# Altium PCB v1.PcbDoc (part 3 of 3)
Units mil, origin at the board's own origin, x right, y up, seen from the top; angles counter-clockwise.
Board outline 2610 x 5109 mil, 2 copper layers (Top Layer, Bottom Layer), stack 62 mil thick; 307 components, 181 nets, 763 pads, 1057 vias.
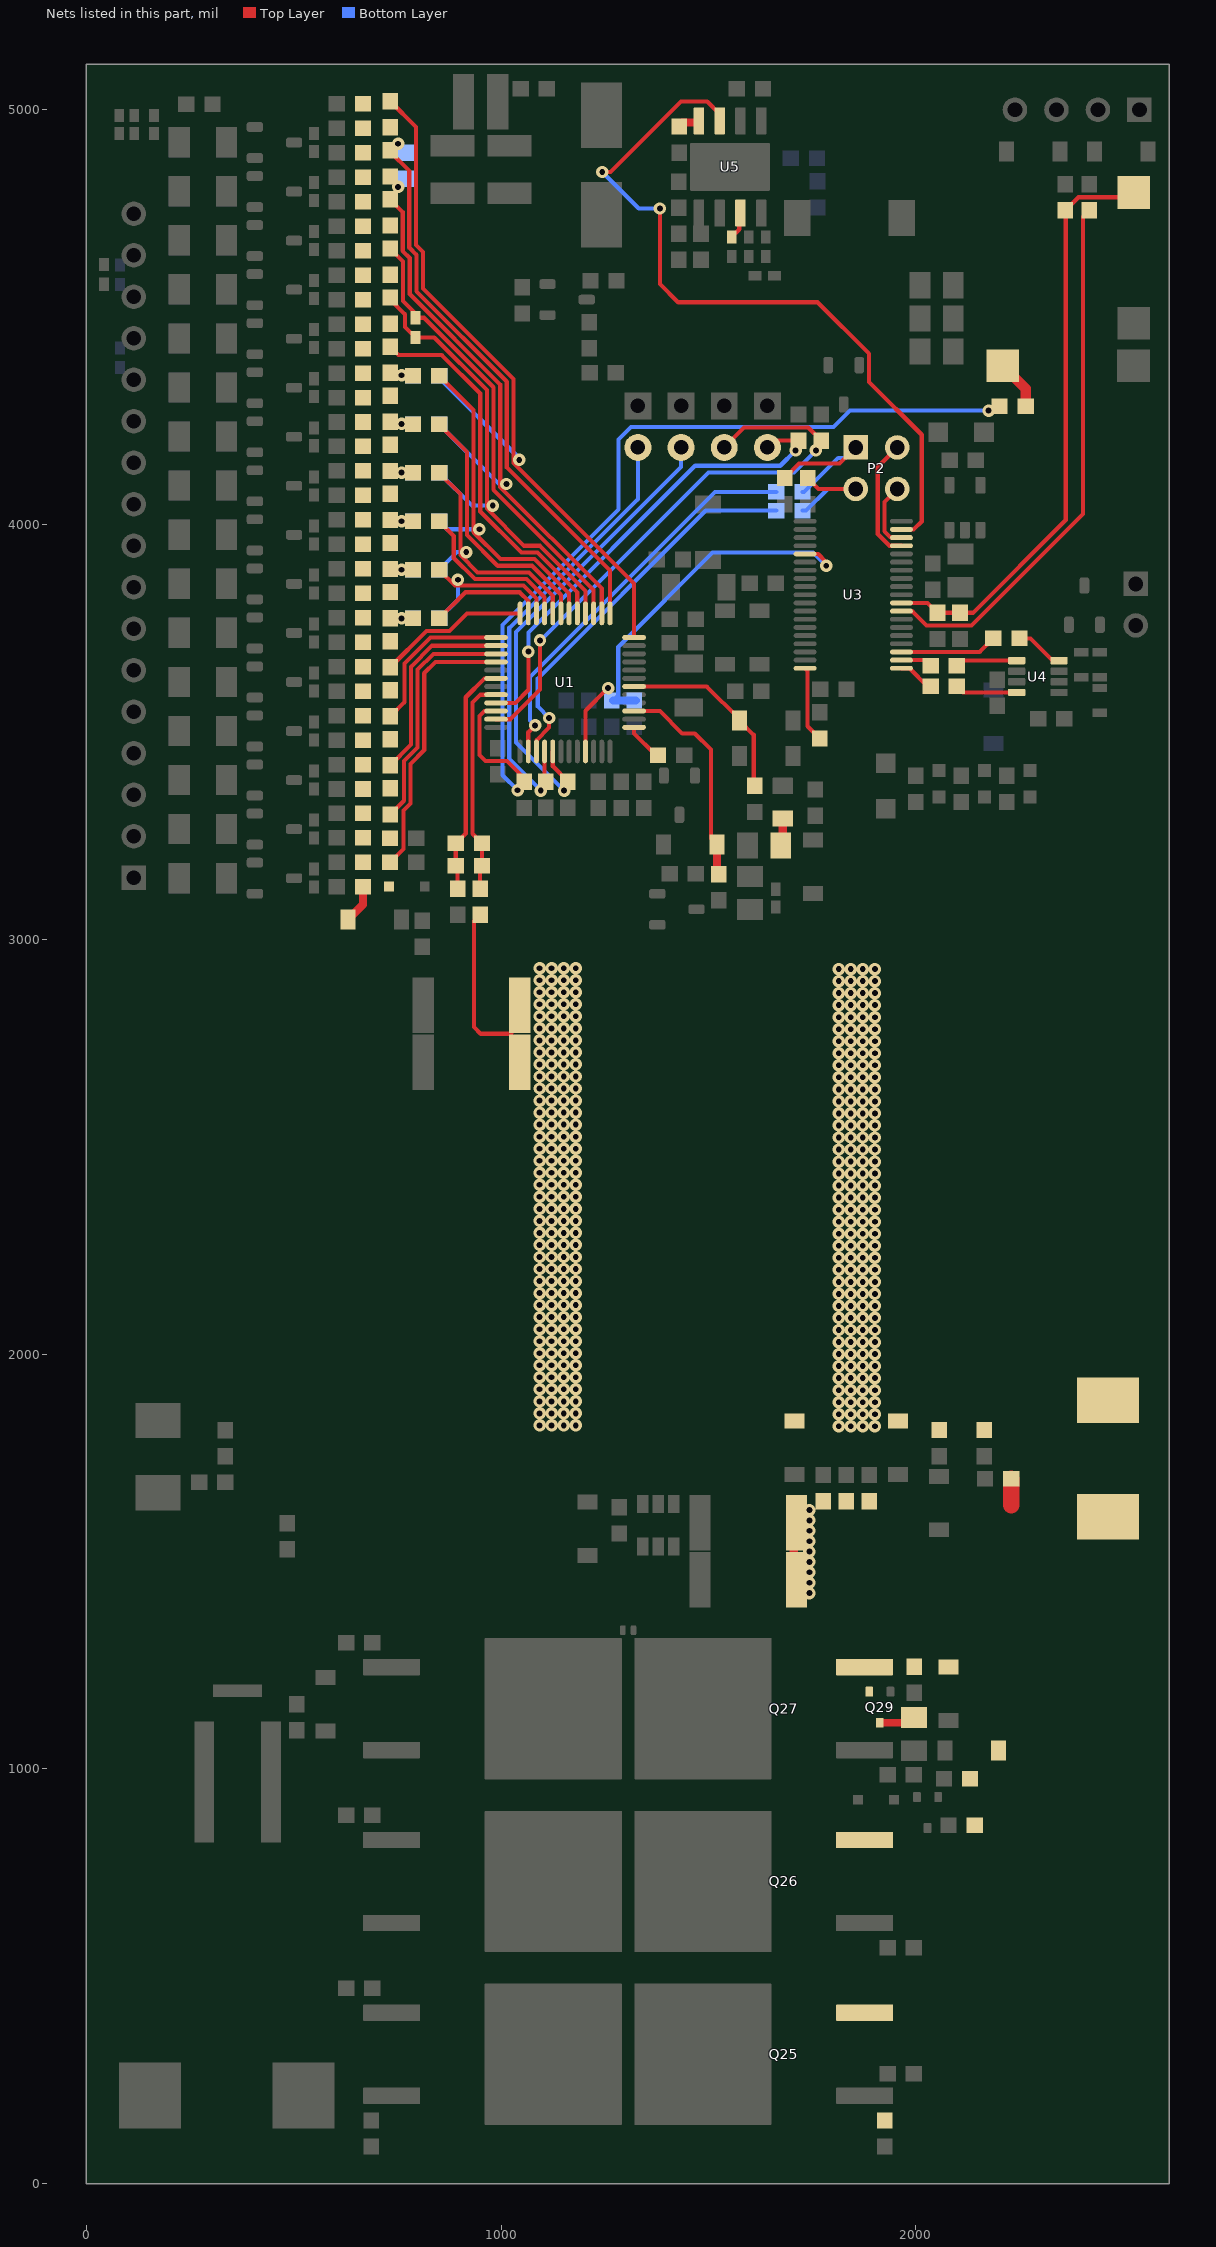
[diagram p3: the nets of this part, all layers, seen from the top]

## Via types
v1: diameter 30, hole 14, Top Layer to Bottom Layer, 1049 vias
v2: diameter 19.68, hole 7.87, Top Layer to Bottom Layer, tented both sides, 4 vias
v3: diameter 19.68, hole 7.87, Top Layer to Bottom Layer, 4 vias

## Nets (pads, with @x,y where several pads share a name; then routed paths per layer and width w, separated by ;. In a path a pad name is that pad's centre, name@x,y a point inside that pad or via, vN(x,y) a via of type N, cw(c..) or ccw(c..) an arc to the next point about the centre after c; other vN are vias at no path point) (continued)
NetQ29_3: Q29.3 R134.2 | length 69.6
  Top Layer w18: Q29.3@1913,1111.6 R134.2@1982.6,1111.6
NetR62_2: R62.2 R64.2 U1.8 | length 607.9
  Top Layer w10: R62.2@850.99,4123.97 902,4072.97 902,3925.63 943.63,3884 1067.86,3884 1124.81,3827.05 U1.8@1124.81,3785.07
  Bottom Layer w10: R64.2@850.99,3890 893.99,3933 v1(916,3933)
NetR63_2: R63.2 R66.2 U1.6 | length 855.9
  Top Layer w10: R63.2@850.99,4358 934,4274.99 934,3980.63 998.63,3916 1081.12,3916 1164.18,3832.94 U1.6@1164.18,3785.07
  Bottom Layer w10: R66.2@850.99,4007 869.99,3988 v1(948,3988)
NetR65_1: R65.1 R67.2 U1.10 | length 410.7
  Top Layer w10: R65.1@850.99,3890.01 889.01,3852 1054.61,3852 1085.44,3821.17 U1.10@1085.44,3785.07
  Bottom Layer w10: R67.2@850.99,3773 896,3818.01 v1(896,3866)
NetR68_1: R68.1 U1.7 | length 625.9
  Top Layer w10: R68.1@850.99,4241.05 918,4174.05 918,3974 992,3900 1074.49,3900 1144.5,3829.99 U1.7@1144.5,3785.07
NetR69_1: R69.1 U1.11 | length 279.6
  Top Layer w10: R69.1@850.99,3773 913.99,3836 1045,3836 1065.76,3815.24 U1.11@1065.76,3785.07
NetR70_1: R70.1 U1.9 | length 400
  Top Layer w10: R70.1@850.99,4007.03 886,3972.02 886,3919 937,3868 1061.24,3868 1105.13,3824.11 U1.9@1105.13,3785.07
NetR84_1: R84.1 S1.1 | length 120.8
  Top Layer w25: S1.1@2209.52,4382 2264.5,4327.02 R84.1@2264.5,4284
NetR87_2: R87.2 U1.26 | length 969.7
  Top Layer w10: U1.26@1065.76,3452.39 1065.76,3498.76 v1(1082,3515)
  Bottom Layer w10: v1(1082,3515) 1070,3527 1070,3632.25 1515.75,4078 R87.2@1663.5,4078
NetR88_2: R88.2 U1.27 | length 942.3
  Top Layer w10: U1.27@1085.44,3452.39 1085.44,3479.25 1116,3509.81 v1(1116,3533)
  Bottom Layer w10: v1(1116,3533) 1088.69,3560.31 1088.69,3628.31 1493.37,4033 R88.2@1663.5,4033
NetR93_1: R93.1 U1.37 | length 89
  Top Layer w10: U1.37@1320.68,3510.46 1320.68,3495.93 1370.61,3446 R93.1@1374.5,3446
NetR105_1: R105.1 U4.8 | length 117.9
  Top Layer w10: R105.1@2249.5,3725 2275.82,3725 2329.43,3671.39 U4.8@2345.18,3671.39
NetR106_1: R106.1 U4.4 | length 150.3
  Top Layer w10: R106.1@2098.5,3609 2112.88,3594.61 U4.4@2242.82,3594.61
NetR107_1: R107.1 U4.1 | length 149.5
  Top Layer w10: R107.1@2098.5,3659 2110.88,3671.39 U4.1@2242.82,3671.39
NetR116_2: R116.2 U5.4 | length 41.2
  Top Layer w20: R116.2@1435.79,4968.28 U5.4@1477,4968.28
NetR117_1: R117.1 U5.7 | length 71.4
  Top Layer w10: R117.1@1556,4692.62 1574.19,4710.81 1574.19,4753.72 U5.7@1577,4753.72
NetR132_2: R132.2 R133.2 | length 60.1
  Top Layer w20: R133.2@1679,3230.5 R132.2@1679,3290.63
PACK: D43.1 R139.1 U1.42 | length 452.4
  Top Layer w10: U1.42@1320.68,3608.89 1495.74,3608.89 1574.53,3530.1 D43.1@1574.53,3527 1609,3492.53 R139.1@1609,3378.51
PACK+: C58.1 C60.1 D39.2 D40.2 D47.1 Q25.3 Q26.3 Q27.3 Q29.2 R127.1 R128.1 R131.2 R135.2 R137.1 R140.2 R141.2 R142.2 | length 201.9
  Top Layer w20: R127.1@1705.77,1582.18 1705.77,1454.7 R128.1@1713.47,1462.4
  Top Layer w40: 2229.5,1635.5 C60.1@2229.5,1699
  other v1: 1743.28,1424 1743.28,1449 1743.28,1474 1743.28,1499 1743.28,1524 1743.28,1549 1743.28,1574 1743.28,1599 1743.28,1624
PACK-: C59.2 D45.2 D46.2 D47.2 R95.1 R112.2 R113.2 R136.1 | length 373.1
  Top Layer w10: R95.1@949.5,3058.5 935,3044.01 935,2788 951,2772 1025,2772
  other v1: 1814,1826 1843,1826 1872,1826 1901,1826 1093,1828 1122,1828 1151,1828 1180,1828 1814,1855 1843,1855 1872,1855 1901,1855 1093,1857 1122,1857 1151,1857 1180,1857 1814,1884 1843,1884 1872,1884 1901,1884 1093,1886 1122,1886 1151,1886 1180,1886 1814,1913 1843,1913 1872,1913 1901,1913 1093,1915 1122,1915 1151,1915 1180,1915 1814,1942 1843,1942 1872,1942 1901,1942 1093,1944 1122,1944 1151,1944 1180,1944 1814,1971 1843,1971 1872,1971 1901,1971 1093,1973 1122,1973 1151,1973 1180,1973 1814,2000 1843,2000 1872,2000 1901,2000 1093,2002 1122,2002 1151,2002 1180,2002 1814,2029 1843,2029 1872,2029 1901,2029 1093,2031 1122,2031 1151,2031 1180,2031 1814,2058 1843,2058 1872,2058 1901,2058 1093,2060 1122,2060 1151,2060 1180,2060 1814,2087 1843,2087 1872,2087 1901,2087 1093,2089 1122,2089 1151,2089 1180,2089 1814,2116 1843,2116 1872,2116 1901,2116 1093,2118 1122,2118 1151,2118 1180,2118 1814,2145 1843,2145 1872,2145 1901,2145 1093,2147 1122,2147 1151,2147 1180,2147 1814,2174 1843,2174 1872,2174 1901,2174 1093,2176 1122,2176 1151,2176 1180,2176 1814,2203 1843,2203 1872,2203 1901,2203 1093,2205 1122,2205 1151,2205 1180,2205 1814,2232 1843,2232 1872,2232 1901,2232 1093,2234 1122,2234 1151,2234 1180,2234 1814,2261 1843,2261 1872,2261 1901,2261 1093,2263 1122,2263 1151,2263 1180,2263 1814,2290 1843,2290 1872,2290 1901,2290 1093,2292 1122,2292 1151,2292 1180,2292 1814,2319 1843,2319 1872,2319 1901,2319 1093,2321 1122,2321 1151,2321 1180,2321 1814,2348 1843,2348 1872,2348 1901,2348 1093,2350 1122,2350 1151,2350 1180,2350 1814,2377 1843,2377 1872,2377 1901,2377 1093,2379 1122,2379 1151,2379 1180,2379 1814,2406 1843,2406 1872,2406 1901,2406 1093,2408 1122,2408 1151,2408 1180,2408 1814,2435 1843,2435 1872,2435 1901,2435 1093,2437 1122,2437 1151,2437 1180,2437 1814,2464 1843,2464 1872,2464 1901,2464 1093,2466 1122,2466 1151,2466 1180,2466 1814,2493 1843,2493 1872,2493 1901,2493 1093,2495 1122,2495 1151,2495 1180,2495 1814,2522 1843,2522 1872,2522 1901,2522 1093,2524 1122,2524 1151,2524 1180,2524 1814,2551 1843,2551 1872,2551 1901,2551 1093,2553 1122,2553 1151,2553 1180,2553 1814,2580 1843,2580 1872,2580 1901,2580 1093,2582 1122,2582 1151,2582 1180,2582 1814,2609 1843,2609 1872,2609 1901,2609 1093,2611 1122,2611 1151,2611 1180,2611 1814,2638 1843,2638 1872,2638 1901,2638 1093,2640 1122,2640 1151,2640 1180,2640 1814,2667 1843,2667 1872,2667 1901,2667 1093,2669 1122,2669 1151,2669 1180,2669 1814,2696 1843,2696 1872,2696 1901,2696 1093,2698 1122,2698 1151,2698 1180,2698 1814,2725 1843,2725 1872,2725 1901,2725 1093,2727 1122,2727 1151,2727 1180,2727 1814,2754 1843,2754 1872,2754 1901,2754 1093,2756 1122,2756 1151,2756 1180,2756 1814,2783 1843,2783 1872,2783 1901,2783 1093,2785 1122,2785 1151,2785 1180,2785 1814,2812 1843,2812 1872,2812 1901,2812 1093,2814 1122,2814 1151,2814 1180,2814 1814,2841 1843,2841 1872,2841 1901,2841 1093,2843 1122,2843 1151,2843 1180,2843 1814,2870 1843,2870 1872,2870 1901,2870 1093,2872 1122,2872 1151,2872 1180,2872 1814,2899 1843,2899 1872,2899 1901,2899 1093,2901 1122,2901 1151,2901 1180,2901 1814,2928 1843,2928 1872,2928 1901,2928 1093,2930 1122,2930 1151,2930 1180,2930
PDSG: D33.1 R125.1 U1.39 | length 531.9
  Top Layer w10: U1.39@1320.68,3549.83 1382.79,3549.83 1436.63,3496 1467,3496 1506.21,3456.79 1506.21,3242.26 D33.1@1520.47,3228
  Top Layer w20: D33.1@1520.47,3228 1520.47,3161.25 R125.1@1525,3156.71
POW_EN: U3.18 U5.3 | length 1831.1
  Top Layer w10: v1(1244,4849) 1264,4849 1434,5019 1497,5019 1527,4989 U5.3@1527,4968.28 ; v1(1383,4761) 1383,4579 1427,4535 1763,4535 1887,4411 1887,4342.63 2014,4215.63 2014,4007 1994.48,3987.48 U3.18@1965.14,3987.48
  Bottom Layer w10: v1(1244,4849) 1332,4761 v1(1383,4761)
PTC_Pull: R108.2 U3.38 | length 184.3
  Top Layer w10: U3.38@1732.86,3652.83 1738.82,3646.87 1738.3,3646.35 1738.3,3513.2 R108.2@1768,3483.5
RXD: R106.2 U3.1 | length 81
  Top Layer w10: U3.1@1965.14,3652.83 1984.17,3652.83 R106.2@2028,3609
SBCLK: R97.1 U3.8 | length 1301.6
  Top Layer w10: U3.8@1965.14,3790.63 1991.02,3790.63 2025.84,3755.81 2133.81,3755.81 2403,4025 2403,4740.99 R97.1@2418.47,4756.45
SBIO: C39.1 R98.1 R104.1 S2.1 U3.9 | length 1411.3
  Top Layer w10: U3.9@1965.14,3810.31 2028.18,3810.31 C39.1@2052,3786.5 R104.1@2106.2,3786.5 2137.5,3786.5 2361,4010 R98.1@2361,4756.45 ; R98.1@2360,4756.45 2391.55,4788 S2.1@2513.52,4788
SCL: P2.1 R87.1 R103.2 | length 338.9
  Top Layer w10: R103.2@1684,4111.5 1718.5,4146 1816,4146 P2.1@1855,4185
  Bottom Layer w10: R87.1@1726.5,4078 1730.63,4078 1812.63,4160 P2.1@1830,4160
SCL_MCU: P2.2 U3.16 | length 296.9
  Top Layer w10: P2.2@1955,4185 1908,4138 1908,3976.37 1936.26,3948.11 U3.16@1965.14,3948.11
SDA: P2.3 R88.1 R102.2 | length 295.4
  Top Layer w10: R102.2@1739,4111.5 1765.5,4085 P2.3@1855,4085
  Bottom Layer w10: R88.1@1726.5,4033 1735.44,4033 1787.44,4085 P2.3@1855,4085 P2.3@1842,4072
SDA_MCU: P2.4 U3.17 | length 162.3
  Top Layer w10: P2.4@1955,4085 1924,4054 1924,3983 1939.2,3967.8 U3.17@1965.14,3967.8
SHUT: C24.1 R90.2 U1.33 U3.24 | length 1041.5
  Top Layer w10: U1.33@1203.55,3452.39 1203.55,3550.55 v1(1258,3605) ; U3.24@1732.86,3928.43 1764.57,3928.43 1783.62,3909.38 1783.62,3900.38 v1(1784,3900)
  Bottom Layer w10: C24.1@1270.38,3574.99 1282.49,3587.11 1282.49,3704.49 1510,3932 1752,3932 v1(1784,3900)
  Bottom Layer w20: C24.1@1270.38,3574.99 R90.2@1325,3574.99
SRN: C32.2 C33.2 R95.2 U1.20 | length 524.8
  Top Layer w10: R95.2@949.5,3121.5 949.5,3172.5 C32.2@953.99,3177 C33.2@953.99,3231 931,3253.99 931,3570 950.2,3589.2 U1.20@988,3589.2
SRP: C32.1 C33.1 R96.2 U1.18 | length 565.2
  Top Layer w10: R96.2@895.5,3121.5 895.5,3172.5 C32.1@891,3177 C33.1@891,3231 915,3255 915,3583 960.57,3628.57 U1.18@988,3628.57
STB: R105.2 U3.3 | length 234.9
  Top Layer w10: U3.3@1965.14,3692.2 2153.71,3692.2 R105.2@2186.5,3725
TS1: C28.1 RT1.2 U1.21 | length 1136.7
  Top Layer w10: U1.21@988,3569.52 1034.52,3569.52 1066,3601 v1(1066,3693) ; RT1.2@1642,4185 1658.52,4201.52 C28.1@1717,4201.52
  Bottom Layer w10: v1(1066,3693) 1066,3739 1468,4141 1673,4141 v1(1710,4178)
TS2: C30.1 RT2.2 U1.23 | length 1375.8
  Top Layer w10: U1.23@987.85,3530 U1.23@988,3530.15 1022.52,3530.15 1094,3601.63 v1(1094,3720) ; RT2.2@1538,4185 1586,4233 1740.52,4233 C30.1@1772,4201.52
  Bottom Layer w10: v1(1094,3720) 1095,3720 1500,4125 1706,4125 v1(1759,4178)
TS3: C31.1 RT3.2 U1.28 | length 1061
  Top Layer w10: U1.28@1105.13,3452.39 1105.13,3382.37 C31.1@1108,3379.5
  Bottom Layer w10: v1(1096,3358) 1020,3434 1020,3750.37 1330,4060.37 RT3.2@1330,4185
TS4: C34.1 RT4.2 U1.29 | length 1127.8
  Top Layer w10: U1.29@1124.81,3452.39 1124.81,3416.63 1161,3380.44 C34.1@1161,3379.5
  Bottom Layer w10: v1(1152,3358) 1036,3474 1036,3740 1434,4138 RT4.2@1434,4185
TXD: R107.2 U3.2 | length 56.8
  Top Layer w10: U3.2@1965.14,3672.52 R107.2@2021.98,3672.52
VC0: C1.1 D9.1 D10.1 R17.2 R18.2 U1.16 | length 768.2
  Top Layer w10: C1.1@732.5,3185 764.81,3217.31 764.81,3309.69 782,3326.88 782,3422.53 815,3455.53 815,3641 841.94,3667.94 U1.16@988,3667.94
  Top Layer w20: D10.1@631.53,3047 667.5,3082.96 R17.2@667.5,3126
VC1: C2.2 C9.1 R19.2 R20.2 U1.15 | length 581.3
  Top Layer w10: C2.2@733,3300.5 766,3333.5 766,3429.16 799,3462.16 799,3649.75 836.88,3687.63 U1.15@988,3687.63
VC2: C2.1 C3.2 R21.2 R22.2 U1.14 | length 484.4
  Top Layer w10: C3.2@733,3418.79 783,3468.79 783,3656.37 833.94,3707.31 U1.14@988,3707.31
VC3: C3.1 C4.2 R23.2 R24.2 U1.13 | length 388.1
  Top Layer w10: C4.2@733,3537.08 767,3571.08 767,3664 830,3727 U1.13@988,3727
VC4: C4.1 C5.2 R25.2 R26.2 U1.12 | length 366.8
  Top Layer w10: C5.2@733,3655.36 820.64,3743 876,3743 918.07,3785.07 U1.12@1046.07,3785.07
VC5: C5.1 C6.2 R27.2 R28.2 R67.1 R69.2 | length 54.4
  Top Layer w20: C6.2@733.65,3773 R69.2@788,3773
  other v1: 760.27,3773
VC6: C6.1 C7.2 R29.2 R30.2 R64.1 R65.2 | length 53.1
  Top Layer w20: C7.2@734.92,3890.01 R65.2@788,3890.01
  other v1: 760.27,3890.2
VC7: C7.1 C8.2 R31.2 R32.2 R66.1 R70.2 | length 51.8
  Top Layer w20: C8.2@736.19,4007.03 R70.2@788,4007.03
  other v1: 760.27,4007.4
VC8: C8.1 C10.2 R33.2 R50.1 R51.2 R62.1 | length 50.5
  Top Layer w20: C10.2@737.53,4123.97 R62.1@788,4123.97
  other v1: 760.27,4124.6
VC9: C10.1 C11.2 R49.1 R52.2 R53.2 R68.2 | length 49.3
  Top Layer w20: C11.2@738.74,4241.05 R68.2@788,4241.05
  other v1: 760.27,4241.8
VC10: C11.1 C12.2 R48.1 R54.2 R55.2 R63.1 | length 47.9
  Top Layer w20: C12.2@740.08,4358 R63.1@788,4358
  other v1: 760.27,4359
VC11: C12.1 C13.2 R56.2 R57.2 U1.5 | length 913.3
  Top Layer w10: C12.1@733,4428.07 753.07,4408 857,4408 950,4315 950,4031 1049,3932 1087.75,3932 1183.87,3835.88 U1.5@1183.87,3785.07
VC12: C13.1 C14.2 R46.1 R50.2 R58.2 R59.2 U1.4 | length 1167
  Top Layer w10: C13.1@733,4546.35 733,4542 769,4506 769,4475.38 R46.1@794,4450.38 839.11,4450.38 966,4323.49 966,4037.63 1055.63,3948 1094.37,3948 1203.55,3838.82 U1.4@1203.55,3785.07
  Bottom Layer w10: R50.2@850.99,4124 929.99,4045 v1(980,4045)
VC13: C14.1 C20.2 R46.2 R60.2 R78.2 U1.3 | length 1094.6
  Top Layer w10: C14.1@733,4664.64 764,4633.64 764,4537.98 794,4507.98 R46.2@794,4497.62 814.5,4497.62 982,4330.12 982,4083 1223.24,3841.76 U1.3@1223.24,3785.07
VC14: C20.1 C21.2 R35.2 R49.2 R79.2 R80.2 U1.2 | length 1430.7
  Top Layer w10: C20.1@733,4782.92 763,4752.92 763,4659 780,4642 780,4554.75 998,4336.75 998,4089.63 1242.92,3844.71 U1.2@1242.92,3785.07
  Bottom Layer w10: R49.2@850.99,4241 994.99,4097 v1(1013,4097)
  other v1: 752,4813
VC15: C21.1 C22.2 R35.1 R81.2 R82.2 U1.1 | length 1331.3
  Top Layer w10: C21.1@733,4897 779,4851 779,4666.37 796,4649.37 796,4561.37 1014,4343.37 1014,4137 1262.61,3888.39 U1.1@1262.61,3785.07
  other v1: 752,4917
VC16: C22.1 R48.2 R83.2 U1.48 | length 1818.9
  Top Layer w10: C22.1@733,5019.5 795,4957.5 795,4673 812,4656 812,4568 1030,4350 1030,4148 1320.68,3857.32 U1.48@1320.68,3727
  Bottom Layer w10: R48.2@850.99,4358 850.99,4352.01 1044,4159 v1(1044,4155)
WAKE: C17.1 R84.2 U1.22 | length 2175.5
  Top Layer w10: U1.22@988,3549.83 959.83,3549.83 948,3538 948,3444 962.46,3429.54 1014.46,3429.54 1056.34,3387.66 C17.1@1056.34,3379.23
  Bottom Layer w10: v1(1040,3359) 1004,3395 1004,3757 1283,4036 1283,4204 1313,4234 1801,4234 1841,4274 v1(2175,4274)
pads on no net: RT5.1S RT5.2S U1.19 U1.40 U1.44 U3.12 U3.13 U3.14 U3.15 U3.25 U3.26 U3.27 U3.29 U3.30 U3.31 U3.32 U3.33 U3.34 U3.35 U3.37 U5.6 U5.9@1552,4861

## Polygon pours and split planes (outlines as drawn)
NetD32_1 on Top Layer "Top Layer-No Net 7" (solid, remove dead copper, pour order 28): 654,1399 654,1135 488,1135 488,1231 536,1279 536,1399
GND on Top Layer "Top Layer-No Net 18" (solid, remove dead copper, pour order 100): 2600,4525 2600,3511 2166,3511 2136,3541 2136,3729 2420,4013 2420,4525
GND on Top Layer "Top Layer-No Net 23" (solid, remove dead copper, pour order 80): 1185.73,4638 868,4638 868,4095 1185.73,4095
NetC44_1 on Top Layer "Top Layer-No Net 16" (solid, remove dead copper, pour order 76): 936,4886 936,5085 778,5085 778,5070 830,5018 830,4886
NetC45_1 on Top Layer "Top Layer-No Net 17" (solid, remove dead copper, pour order 60): 967,5085 967,4886 1075,4886 1075,5085
GND on Top Layer "Top Layer-No Net 19" (solid, remove dead copper, pour order 64): 1404,4796 1273,4665 830,4665 830,4825 1254,4825 1362.49,4933.49 1649,4935 1649,4796
PACK+ on Top Layer "Top Layer-No Net 11" (solid, remove dead copper, pour order 38): 2589,126 2589,268 2589,1665 1680,1665 1680,126
NetC57_2 on Top Layer "Top Layer-No Net 10" (solid, remove dead copper, pour order 36): 422,1119.44 861,1119.44 861,25 422,25
PACK- on Top Layer "Top Layer-No Net 9" (solid, pour order 32): 1019,3003 1019,1794 2590,1794 2590,3003
BAT+ on Top Layer "Top Layer-No Net 6" (solid, pour order 26): 29,1710 29,19 399,19 399,1025 292,1132 292,1710
GND on Top Layer "Top Layer-No Net 4" (solid, remove dead copper, pour order 10): 1795.27,3060 1795.27,3576.73 1752,3620 1752,4173 2139,4173 2139,3690 1895,3690 1895,3060
GND on Top Layer "Top Layer-No Net 2" (solid, remove dead copper, pour order 6): 1241,4553 1241,4038 1309,3970 1801,3970 1801,4553
NetD34_1 on Top Layer "Top Layer-No Net 1" (solid, pour order 2): 1356,1558 1325,1589 1182,1589 1182,1496 1356,1496
GND on Top Layer "Top Layer-No Net 13" (solid, remove dead copper, pour order 42): 776,3297 776,3792 1342,3792 1342,3437 904,3437 904,3297
GND on Top Layer "Top Layer-No Net 14" (solid, remove dead copper, pour order 44): 982.48,3023 982.48,3269 944,3269 944,3419 1410,3419 1410,3023
GND on Top Layer "Top Layer-No Net 3" (solid, remove dead copper, pour order 46): 776,3023 776,3338 904,3338 904,3255.7 865.32,3255.7 865.32,3023
NetD38_1 on Top Layer "Top Layer-No Net" (solid, remove dead copper, pour order 82): 2093.54,1072.52 2093.54,957 1963,957 1963,1072.52
NetQ24_1 on Top Layer "Top Layer-No Net 8" (solid, remove dead copper, pour order 84): 1363,1713 1363,1389 1566,1389 1566,1713
NetD34_1 on Top Layer "Top Layer-No Net 12" (solid, remove dead copper, pour order 90): 1664,57 1664,1346 1634,1376 1225,1376 1093,1508 1093,1673 1029,1737 887,1737 887,57
GND on Top Layer "Top Layer-No Net 15" (solid, pour order 92): 1449,3880 1449,3693 1650,3693 1662,3681 1662,3430 1682,3410 1722,3410 1722,3880
NetC50_2 on Top Layer "Top Layer-No Net 22" (solid, remove dead copper, pour order 94): 1410,4783 1501,4783 1501,4681 1410,4681
GND on Top Layer "Top Layer-No Net 21" (solid, remove dead copper, pour order 68): 2057,4753 2014,4796 1610,4796 1610,5079 2157,5079 2157,4384 2057,4384
GND on Bottom Layer "Bottom Layer-No Net 1" (solid, remove dead copper, pour order 102): 1719,4649 1107,4649 1107,5080 1719,5080
GND on Bottom Layer "Bottom Layer-No Net 6" (solid, remove dead copper, pour order 74): 792,5053 880,4965 880,4648 1048,4648 1048,5082 792,5082
GND on Bottom Layer "Bottom Layer-No Net" (solid, remove dead copper, pour order 98): 2187,5082 2600,5082 2600,3022 787,3022 787,4621 1812,4621 2187,4621
PACK- on Bottom Layer "Top Layer-No Net 9" (solid, pour order 34): 955,3003 955,1797 2590,1797 2590,3003
GND on Bottom Layer "Bottom Layer-No Net 3" (solid, remove dead copper, pour order 52): 859,3201 787,3201 787,3022 859,3022
NetD34_1 on Bottom Layer "Bottom Layer-No Net 2" (solid, remove dead copper, pour order 88): 771,1734 645,1608 645,25 1967,25 1967,1367 1213,1367 1196,1384 1196,1579 1041,1734

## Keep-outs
Keep-Out Layer:
  text ".Layer_Name" at 577,-858.49 h60

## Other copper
Top Layer:
  rectangle net CANL: 2493,3726 2600,3786
  rectangle net CANH: 2493,3826 2600,3886
  rectangle net BAT-: 30,1796 839,3003
  rectangle net VC0: 647.5,3104.5 751.5,3205.5
  rectangle net VC1: 648,3221.5 752,3322.5
  rectangle net VC0: 647,3107 688,3204
  rectangle net VC2: 648,3338.29 752,3439.29
  rectangle net VC3: 648,3456.57 752,3557.57
  rectangle net VC4: 648,3574.86 752,3675.86
  rectangle net VC5: 648,3693.14 752,3794.14
  rectangle net VC6: 648,3811.43 752,3912.43
  rectangle net VC7: 648,3929.71 752,4030.71
  rectangle net VC8: 648,4048 752,4149
  rectangle net VC9: 648,4166.29 752,4267.29
  rectangle net VC10: 648,4284.57 752,4385.57
  rectangle net VC11: 648,4402.86 752,4503.86
  rectangle net VC12: 648,4521.14 752,4622.14
  rectangle net VC13: 648,4639.43 752,4740.43
  rectangle net VC14: 648,4757.71 752,4858.71
  rectangle net VC15: 648,4876 752,4977
  rectangle net VC16: 648,4994 752,5039
  rectangle net NetD34_2: 1183,1610 1356,1661
  text ".Layer_Name" at 577,-858.49 h60
Bottom Layer:
  rectangle net GND: 1447,4812 1648,4911
  rectangle net NetQ24_1: 1222,1387.34 1563,1692
  rectangle net BAT-: 30,1796 890,3003
  rectangle net NetQ16_3: 280,4877 729,4976.51
  rectangle net NetQ15_3: 262,4749.26 729,4851
  rectangle net NetQ6_3: 263,3685.94 736,3794.94
  rectangle net NetQ7_3: 262,3804.2 736,3913.2
  rectangle net NetQ8_3: 262,3922.46 736,4031.46
  rectangle net NetQ9_3: 262,4040.71 736,4149.71
  rectangle net NetQ10_3: 262,4158.97 736,4267.97
  rectangle net NetQ11_3: 262,4277.23 736,4386.23
  rectangle net NetQ5_3: 263,3566.68 774,3675.68
  rectangle net NetQ4_3: 263,3448.43 774,3557.43
  rectangle net NetQ3_3: 263,3330.17 774,3439.17
  rectangle net NetQ2_3: 263,3211.91 774,3320.91
  rectangle net NetQ1_3: 263,3093.66 774,3202.66
  rectangle net NetQ13_3: 262,4512.74 775,4621.74
  rectangle net NetQ14_3: 262,4631 814,4740
  rectangle net NetQ12_3: 262,4394.49 775,4503.49
  rectangle net PACK+: 1590,1387 1967,1692
  text ".Layer_Name" at 577,-858.49 h60

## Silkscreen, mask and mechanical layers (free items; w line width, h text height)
Top Overlay:
  text "SCL" at 1871,4248 h30
  text "PACK-" at 2347,2548 h60 r270
  text "BAT-" at 275,2307 h60 r90
  text "PACK+" at 2350,819 h60 r270
  text "BAT+" at 270,500 h60 r90
  text ".Layer_Name" at 577,-858.49 h60
Bottom Overlay:
  text "CAUTION" at 557,234 h60
  text "READ USER GUIDE" at 660,170 h60
  text "BEFPRE USE" at 584,103 h60
  text ".Layer_Name" at 577,-858.49 h60
Top Paste:
  rectangle: 2493,3726 2600,3786
  rectangle: 2493,3826 2600,3886
  rectangle: 2441,2166 2582,2693
  rectangle: 37,2158 178,2685
  rectangle: 34,463 175,990
  rectangle: 2440,463 2581,990
  text ".Layer_Name" at 577,-858.49 h60
Bottom Paste:
  text ".Layer_Name" at 577,-858.49 h60
Top Solder:
  rectangle: 2493,3726 2600,3786
  rectangle: 2493,3826 2600,3886
  rectangle: 2441,2166 2582,2693
  rectangle: 37,2158 178,2685
  rectangle: 34,463 175,990
  rectangle: 2440,463 2581,990
  text ".Layer_Name" at 577,-858.49 h60
  text ".Layer_Name" at 577,-858.49 h60
Bottom Solder:
  text ".Layer_Name" at 577,-858.49 h60
Drill Guide:
  text ".Layer_Name" at 577,-858.49 h60
M1 Board Outline:
  the board outline again, w10
  text ".Layer_Name" at 577,-858.49 h60
M2 Board Dimensions:
  rectangle: 0,-275 125,-150
  rectangle: 125,-400 500,-275
  lines w7: 0,-275 1000,-275 ; 125,-400 125,-150 ; 250,-400 250,-150 ; 500,-400 500,-150 ; 750,-400 750,-150 ; 0,-400 1000,-400 1000,-150 0,-150 0,-400
  text ".Layer_Name" at 577,-858.49 h60
M3 3D STEP Top:
  text ".Layer_Name" at 577,-858.49 h60
M4 3D STEP Bottom:
  text ".Layer_Name" at 577,-858.49 h60
M5 Assembly Top:
  lines w10: -292,-930.17 6308,-930.17 ; -292,-726.83 6310,-726.83 ; -292,-523.5 -292,-1133.5 3713,-1133.5 6310,-1133.5 6310,-523.5 -291.5,-523.5 -291.5,-1133.5 1284,-1133.5 ; 2173,-1133.5 2173,-523.5 ; 3440,-726.83 3440,-523.5 ; 4280,-726.83 4280,-523.5 ; 4902,-1140 4902,-937.17
  text "COMPONENTS MARKED 'DNP' SHOULD NOT BE POPULATED." at 1153.5,-318.5 h60
  text "ASSEMBLY VARIANT:" at 1153,-434 h60
  text ".VariantName" at 2189,-434 h60
  text "PCB VIEWED FROM TOP SIDE" at -228.5,-655.67 h60
  text "BOARD #:" at 2248,-655.67 h60
  text ".PRJ_Number" at 2793.5,-655.67 h60
  text "REV:" at 3638,-655.67 h60
  text ".PCB_Rev" at 3929.5,-655.67 h60
  text "SVN REV:" at 4476,-655.67 h60
  text ".VersionControl_RevNumber" at 4982,-655.67 h60
  text "TID #:" at 2248,-859 h60
  text ".TID" at 2793.5,-859 h60
  text "PLOT NAME =" at -228.5,-1064.34 h60
  text ".plot_File_Name" at 577,-1064.34 h60
  text "GENERATED    :" at 2250,-1064.34 h60
  text ".Print_Date" at 3119.5,-1064.34 h60
  text ".Print_Time" at 3848.5,-1064.34 h60
  text "TEXAS INSTRUMENTS" at 5113,-1064.34 h60
M6 Assembly Bottom:
  lines w10: -292.5,-727.33 6309.5,-727.33 ; -290.5,-930.67 6309.5,-930.67 ; 1115.5,-1140.5 1115.5,-937.67 ; 1737.5,-727.33 1737.5,-524 ; 2577.5,-727.33 2577.5,-524 ; 3844.5,-1134 3844.5,-524 ; 4733.5,-1134 6309,-1134 6309,-524 -292.5,-524 -292.5,-1134 2304.5,-1134 6309.5,-1134 6309.5,-524
  text "COMPONENTS MARKED 'DNP' SHOULD NOT BE POPULATED." at 6102,-318 h60
  text ".VariantName" at 5058,-434 h60
  text "ASSEMBLY VARIANT:" at 6097,-434 h60
  text ".VersionControl_RevNumber" at 1035.5,-656.17 h60
  text "SVN REV:" at 1541.5,-656.17 h60
  text ".PCB_Rev" at 2088,-656.17 h60
  text "REV:" at 2379.5,-656.17 h60
  text ".PRJ_Number" at 3224,-656.17 h60
  text "BOARD #:" at 3769.5,-656.17 h60
  text "PCB VIEWED FROM BOTTOM SIDE" at 6246,-656.17 h60
  text ".TID" at 3224,-859.5 h60
  text "TID #:" at 3769.5,-859.5 h60
  text "TEXAS INSTRUMENTS" at 904.5,-1064.84 h60
  text ".Print_Time" at 2169,-1064.84 h60
  text ".Print_Date" at 2898,-1064.84 h60
  text "GENERATED    :" at 3767.5,-1064.84 h60
  text ".plot_File_Name" at 5440.5,-1064.84 h60
  text "PLOT NAME =" at 6246,-1064.84 h60
M9 Title Sheet:
  drawing of 57 lines, arcs and shapes, not listed
  text "1" at 739.84,8036.5 h70
  text "2" at 3235.5,8036.5 h70
  text "3" at 5724.84,8036.5 h70
  text "4" at 8231.51,8036.5 h70
  text "5" at 10730.5,8036.5 h70
  text "6" at 13235.5,8036.5 h70
  text "A" at -416.5,6893.5 h70
  text "A" at 14383.5,6893.5 h70
  text "B" at -416.5,4513.5 h70
  text "B" at 14383.5,4513.5 h70
  text "C" at -416.5,2138.5 h70
  text "C" at 14383.5,2138.5 h70
  text "PROJECT TITLE:" at 11343.5,277.5 h45
  text ".PRJ_Title" at 11393.5,144.17 h70
  text "DESIGNED FOR:" at 11343.5,-23.5 h45
  text ".PRJ_Customer" at 11393.5,-163.5 h70
  text "D" at -416.5,-231.5 h70
  text "D" at 14383.5,-231.5 h70
  text "FILE NAME:" at 11343.5,-323.5 h45
  text ".PCB_File_Name_No_Path" at 11393.5,-443.5 h70
  text "Texas Instruments (TI) and/or its licensors do not warrant the accuracy or completeness of this specification" at 6374,-605.34 h45
  text "ENGINEER:" at 11343.5,-613.5 h45
  text "LAYOUT BY:" at 12848.5,-613.5 h45
  text "or any information contained therein. TI and/or its licensors do not warrant that this design will meet" at 6329.01,-718 h45
  text ".PRJ_Engineer" at 11393.5,-768.49 h70
  text ".PCB_Layout" at 12899,-768.49 h70
  text "the specifications, will be suitable for your application or fit for any particular purpose, or will operate in" at 6329.01,-830.67 h45
  text ".Layer_Name" at 577,-858.49 h60
  text "ALTIUM DESIGNER VERSION:" at 12848.5,-923.5 h45
  text "an implementation. TI and/or its licensors do not warrant that the design is production worthy. You should" at 6329.01,-943.33 h45
  text "completely validate and test your design implementation to confirm the system functionality for your application." at 6374,-1056 h45
  text ".print_Scale" at 11393.5,-1056.83 h70
  text ".Application_BuildNumber" at 12899,-1056.83 h70
  text "1" at 739.84,-1263.5 h70
  text "2" at 3235.5,-1263.5 h70
  text "3" at 5724.84,-1263.5 h70
  text "4" at 8231.51,-1263.5 h70
  text "5" at 10730.5,-1263.5 h70
  text "6" at 13235.5,-1263.5 h70
M10 Fab Notes:
  drawing of 189 lines, arcs and shapes, not listed
  text "DESIGN INFORMATION" at 12382.02,6356.17 h60
  text "MIN. TRACK WIDTH:" at 11737.46,6224.05 h60
  text "8" at 12833.7,6224.05 h60
  text "MIL" at 12988.46,6224.05 h60
  text "MIN. CLEARANCE:" at 11737.46,6099.92 h60
  text "0.2" at 12773.7,6099.93 h60
  text "mm" at 12988.46,6099.92 h60
  text "MIN. VIA PAD SIZE:" at 11737.46,5975.8 h60
  text "24" at 12803.71,5975.8 h60
  text "MIL" at 12988.46,5975.8 h60
  text "0.05mm (2MIL)" at 12432.46,5845.9 h60
  text "MINIMUM ANNULAR RING" at 11408.23,5837.67 h60
  text "EXTERNAL" at 13140.46,5837.67 h60
  text "PER" at 11608.23,5727.55 h60
  text "IPC-D-275 CLASS 2 LEVEL C" at 11828.23,5727.54 h60
  text "MIL, HOLES" at 13316.46,5627.07 h60
  text "+/-" at 12924,5618.48 h60
  text "+/-" at 13778,5618.48 h60
  text "REGISTRATION TOLERANCES:" at 11408.23,5617.42 h60
  text "METAL" at 12608,5617.42 h60
  text "5" at 13184.2,5617.42 h60
  text "3" at 14017.2,5617.42 h60
  text "MIL" at 14133.46,5617.42 h60
  text "HOLE SIZE TOLERANCE (UNLESS OTHERWISE SPECIFIED):" at 11408.23,5519.1 h60
  text "+/-" at 13778,5516.23 h60
  text "3" at 14017.2,5515.17 h60
  text "MIL" at 14133.46,5515.17 h60
  text "MATERIAL:" at 11333.46,5377.52 h60
  text "FR-4 High Tg" at 12319.9,5249 h60
  text "X" at 12175.46,5241.01 h60
  text "FR-408" at 11754.46,5236.49 h60
  text "OTHER" at 13242.46,5236.49 h60
  text "62 MIL (1.6mm) +/-10%" at 12074.56,5093.46 h60
  text "X" at 11954.46,5091.01 h60
  text "THICKNESS:" at 11408.23,5085.24 h60
  text "OTHER" at 13359.46,5085.24 h60
  text "TOLERANCE:" at 11408.23,4946.92 h60
  text "X" at 12256.46,4946.92 h60
  text "ANSI IPC-6012 TYPE 3 CLASS 2" at 12434.48,4946.92 h60
  text "OTHER +/-" at 12434.46,4802.73 h60
  text "BOW & TWIST:" at 11408.23,4657.54 h60
  text "X" at 12256.46,4657.54 h60
  text "ANSI IPC-6012 TYPE 3 CLASS 2" at 12434.48,4657.54 h60
  text "OTHER +/-" at 12434.46,4510.85 h60
  text "DRILLING:" at 11333.46,4380.23 h60
  text "NC_DRILL FILES" at 13094.46,4275.04 h60
  text "REFERENCE:" at 11408.23,4271.1 h60
  text "X" at 12065.46,4271.01 h60
  text "AS SHOWN" at 12243.46,4271.1 h60
  text "X" at 12966.46,4271.1 h60
  text "OTHER" at 13392.46,4128.85 h60
  text "PTH COPPER THICKNESS:" at 11407.91,4125.32 h60
  text "X" at 12547.14,4125.32 h60
  text "20-30 um" at 12675.14,4125.32 h60
  text "BOARD FINISH:" at 11333.46,3977.73 h60
  text "SILKSCREEN:" at 11488.68,3867.6 h60
  text "X" at 12446.46,3867.6 h60
  text "TOP" at 12563.46,3867.6 h60
  text "X" at 12956.46,3867.6 h60
  text "BOTTOM" at 13074.46,3867.6 h60
  text "SILKSCREEN COLOR:" at 11488.68,3712.41 h60
  text "X" at 12445.46,3712.41 h60
  text "WHITE" at 12563.46,3712.41 h60
  text "OTHER" at 13074.46,3712.41 h60
  text "X" at 12576.46,3568.96 h60
  text "GREEN" at 12694.46,3568.96 h60
  text "OTHER" at 13312.46,3568.96 h60
  text "SOLDER RESIST COLOR:" at 11488.68,3562.1 h60
  text "X" at 12576.46,3414.71 h60
  text "MATTE" at 12694.46,3414.71 h60
  text "SEMI-GLOSS" at 13312,3414.07 h60
  text "IMMERSION GOLD (ENIG)" at 12394.46,3241.94 h60
  text "ENEPIG" at 13732,3234.72 h60
  text "SURFACE FINISH:" at 11333.46,3233.72 h60
  text "X" at 12216.46,3233.72 h60
  text "IMM. TIN/SILVER OR EQUIV" at 11663,3096.4 h60
  text "OTHER" at 13094.46,3092.47 h60
  text "ARRAY/PANEL:" at 11333.46,2937.09 h60
  text "CUT AND TRIM PER M1 BOARD OUTLINE" at 12394.46,2928.87 h60
  text "N.C. ROUTE" at 12394.46,2792.9 h60
  text "X" at 13082.46,2792.9 h60
  text "V. SCORE" at 13260.46,2792.9 h60
  text "CERTIFICATION:" at 11333.46,2663.77 h60
  text "MATERIALS AND WORKMANSHIP FOR ALL PCBS" at 12058.46,2663.77 h60
  text "TO MEET OR EXCEED THE REQUIREMENTS OF:" at 12058.46,2569.71 h60
  text "X" at 11695.97,2441.08 h60
  text "ANSI IPC-A-600F CLASS ->" at 11823.96,2441.08 h60
  text "X" at 13471.97,2441.08 h60
  text "2" at 13581.96,2441.08 h60
  text "1" at 13266.96,2439.58 h60
  text "3" at 13935.96,2439.58 h60
  text "X" at 12507.97,2293.39 h60
  text "RoHS" at 12635.96,2293.39 h60
  text "OTHER" at 13280.36,2293.39 h60
  text "PER ORDER" at 13677.42,2293.39 h60
  text "ALL BOARDS MUST MEET OR EXCEED UL94-V0 REQUIREMENTS." at 11361,2139.57 h60
  text "PCB MUST BEAR THE UL94V-0 UL REGISTERED MATERIAL ID NUMBER" at 11361,2023.5 h60
  text "ADDITIONAL REQUIREMENTS:" at 11333.46,1854.08 h60
  text "MICROSECTION:" at 11408.23,1746.95 h60
  text "YES" at 12313.96,1746.95 h60
  text "REQUIRED" at 13175.46,1602.62 h60
  text "BARE BOARD ELEC. TEST:" at 11408.23,1599.76 h60
  text "NONE" at 12713.96,1599.76 h60
  text "X" at 13057.46,1599.76 h60
  text "PER ORDER" at 13767.46,1599.76 h60
  text "XX MIL VIAS REQUIRE NON-CONDUCTIVE FILL AND PLANARIZE" at 11576.38,1394.82 h59
  text "XX MIL VIAS REQUIRE CONDUCTIVE FILL AND PLANARIZE" at 11584.38,1290.84 h60
  text "OUTER XX MIL TRACES REQUIRE 50 OHM SINGLE-ENDED IMPEDANCE" at 11583.39,1127.46 h58
  text "LAYER 2 & 3 (INNER LAYERS) XX MIL WIDE, XX MIL SPACE / TRACES REQUIRE 100 OHM DIFFERENTIAL IMPEDANCE" at 11575.39,891.74 h60
  text ".Layer_Name" at 577,-858.49 h60
M11 Gerber Information:
  lines w10: -292,-930.17 6308,-930.17 ; -292,-726.83 6310,-726.83 ; -292,-523.5 -292,-1133.5 3713,-1133.5 6310,-1133.5 6310,-523.5 -291.5,-523.5 -291.5,-1133.5 1284,-1133.5 ; 2173,-1133.5 2173,-523.5 ; 3440,-726.83 3440,-523.5 ; 4280,-726.83 4280,-523.5 ; 4902,-1140 4902,-937.17
  text "ALL ARTWORK VIEWED FROM TOP SIDE" at -228.5,-655.67 h60
  text "BOARD #:" at 2248,-655.67 h60
  text ".PRJ_Number" at 2793.5,-655.67 h60
  text "REV:" at 3638,-655.67 h60
  text ".PCB_Rev" at 3929.5,-655.67 h60
  text "SVN REV:" at 4476,-655.67 h60
  text ".VersionControl_RevNumber" at 4982,-655.67 h60
  text "LAYER NAME =" at -228.5,-858.49 h60
  text "TID #:" at 2248,-859 h60
  text ".TID" at 2793.5,-859 h60
  text "PLOT NAME =" at -228.5,-1064.34 h60
  text ".plot_File_Name" at 577,-1064.34 h60
  text "GENERATED    :" at 2250,-1064.34 h60
  text ".Print_Date" at 3119.5,-1064.34 h60
  text ".Print_Time" at 3848.5,-1064.34 h60
  text "TEXAS INSTRUMENTS" at 5113,-1064.34 h60
M12 Stackup:
  drawing of 530 lines, arcs and shapes, not listed
  text "Layer" at 9797.84,7830 h60
  text "Layer" at 9797.84,7830 h60
  text "Name" at 10207.76,7830 h60
  text "Name" at 10207.76,7830 h60
  text "Material" at 11137.5,7830 h60
  text "Material" at 11137.5,7830 h60
  text "Thickness" at 11997.27,7830 h60
  text "Thickness" at 11997.27,7830 h60
  text "Constant" at 12647.1,7830 h60
  text "Constant" at 12647.1,7830 h60
  text "Board Layer Stack" at 13216.96,7830 h60
  text "Board Layer Stack" at 13216.96,7830 h60
  text "Board Layer Stack" at 14336.65,7830 h60
  text "1" at 9797.84,7710 h60
  text "1" at 9797.84,7710 h60
  text "Top Overlay" at 10207.76,7710 h60
  text "Top Overlay" at 10207.76,7710 h60
  text "2" at 9797.84,7590 h60
  text "2" at 9797.84,7590 h60
  text "Top Solder" at 10207.76,7590 h60
  text "Top Solder" at 10207.76,7590 h60
  text "Solder Resist" at 11137.5,7590 h60
  text "Solder Resist" at 11137.5,7590 h60
  text "0.40mil" at 11997.27,7590 h60
  text "0.40mil" at 11997.27,7590 h60
  text "3.5" at 12647.1,7590 h60
  text "3.5" at 12647.1,7590 h60
  text "3" at 9797.84,7470 h60
  text "3" at 9797.84,7470 h60
  text "Top Layer" at 10207.76,7470 h60
  text "Top Layer" at 10207.76,7470 h60
  text "Copper" at 11137.5,7470 h60
  text "Copper" at 11137.5,7470 h60
  text "1.40mil" at 11997.27,7470 h60
  text "1.40mil" at 11997.27,7470 h60
  text "4" at 9797.84,7350 h60
  text "4" at 9797.84,7350 h60
  text "Dielectric1" at 10207.76,7350 h60
  text "Dielectric1" at 10207.76,7350 h60
  text "FR-4" at 11137.5,7350 h60
  text "FR-4" at 11137.5,7350 h60
  text "59.20mil" at 11997.27,7350 h60
  text "59.20mil" at 11997.27,7350 h60
  text "4.8" at 12647.1,7350 h60
  text "4.8" at 12647.1,7350 h60
  text "5" at 9797.84,7230 h60
  text "5" at 9797.84,7230 h60
  text "Bottom Layer" at 10207.76,7230 h60
  text "Bottom Layer" at 10207.76,7230 h60
  text "Copper" at 11137.5,7230 h60
  text "Copper" at 11137.5,7230 h60
  text "1.40mil" at 11997.27,7230 h60
  text "1.40mil" at 11997.27,7230 h60
  text "6" at 9797.84,7110 h60
  text "6" at 9797.84,7110 h60
  text "Bottom Solder" at 10207.76,7110 h60
  text "Bottom Solder" at 10207.76,7110 h60
  text "Solder Resist" at 11137.5,7110 h60
  text "Solder Resist" at 11137.5,7110 h60
  text "0.40mil" at 11997.27,7110 h60
  text "0.40mil" at 11997.27,7110 h60
  text "3.5" at 12647.1,7110 h60
  text "3.5" at 12647.1,7110 h60
  text "7" at 9797.84,6990 h60
  text "7" at 9797.84,6990 h60
  text "Bottom Overlay" at 10207.76,6990 h60
  text "Bottom Overlay" at 10207.76,6990 h60
  text ".Layer_Name" at 577,-858.49 h60
M13 Component Bodies Top:
  text ".Layer_Name" at 577,-858.49 h60
M14 Component Bodies Bottom:
  text ".Layer_Name" at 577,-858.49 h60
M15 Courtyards Top:
  text ".Layer_Name" at 577,-858.49 h60
M16 Courtyards Bottom:
  text ".Layer_Name" at 577,-858.49 h60
Drill Drawing:
  circle w10: c5348.9,3203.16 r22.14
  lines w10: 5326.76,3026.05 5371.04,3026.05 5348.9,2981.77 5326.76,3026.05 ; 5326.76,3092.47 5337.83,3092.47 5348.9,3081.4 5359.97,3092.47 5371.04,3092.47 5359.97,3103.54 5371.04,3114.6 5359.97,3114.6 5348.9,3125.67 5337.83,3114.6 5326.76,3114.6 5337.83,3103.54 5326.76,3092.47 ; 5326.76,3280.64 5348.9,3291.71 5371.04,3280.64 5359.97,3302.78 5371.04,3324.92 5348.9,3313.85 5326.76,3324.92 5337.83,3302.78 5326.76,3280.64
  lines w12: 5286,2951.89 8398.94,2951.89 ; 5286,3350.38 8398.94,3350.38 ; 5601.63,2852.27 5601.63,3450 ; 5918.82,2852.27 5918.82,3450 ; 6540.56,2852.27 6540.56,3450 ; 6784.88,2852.27 6784.88,3450 ; 7145.22,2852.27 7145.22,3450 ; 7854.73,2852.27 7854.73,3450 ; 5286,2852.27 8398.94,2852.27 8398.94,3450 5286,3450 5286,2852.27
  text "Symbol" at 5345.77,3380.26 h72
  text "Quantity" at 5631.52,3380.26 h72
  text "Finished Hole Size" at 5948.7,3380.26 h72
  text "Plated" at 6570.45,3380.26 h72
  text "Hole Type" at 6814.77,3380.26 h72
  text "Drill Layer Pair" at 7175.11,3380.26 h72
  text "Hole Tolerance" at 7884.62,3380.26 h72
  text "8" at 5631.52,3280.64 h60
  text "7.87mil (0.200mm)" at 5948.7,3280.64 h60
  text "PTH" at 6570.45,3280.64 h60
  text "Round" at 6814.77,3280.64 h60
  text "Top Layer - Bottom Layer" at 7175.11,3280.64 h60
  text "1049" at 5631.52,3181.02 h60
  text "14.00mil (0.356mm)" at 5948.7,3181.02 h60
  text "PTH" at 6570.45,3181.02 h60
  text "Round" at 6814.77,3181.02 h60
  text "Top Layer - Bottom Layer" at 7175.11,3181.02 h60
  text "8" at 5631.52,3081.4 h60
  text "35.00mil (0.889mm)" at 5948.7,3081.4 h60
  text "PTH" at 6570.45,3081.4 h60
  text "Round" at 6814.77,3081.4 h60
  text "Top Layer - Bottom Layer" at 7175.11,3081.4 h60
  text "27" at 5631.52,2981.77 h60
  text "35.43mil (0.900mm)" at 5948.7,2981.77 h60
  text "PTH" at 6570.45,2981.77 h60
  text "Round" at 6814.77,2981.77 h60
  text "Top Layer - Bottom Layer" at 7175.11,2981.77 h60
  text "1092 Total" at 5631.52,2882.15 h60
  text ".Layer_Name" at 577,-858.49 h60
M17 Embedded Cavity:
  text ".Layer_Name" at 577,-858.49 h60
M18 Embedded Assembly:
  text ".Layer_Name" at 577,-858.49 h60
M19 Embedded Keepout:
  text ".Layer_Name" at 577,-858.49 h60

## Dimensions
0,-400 to 1000,-400 on M2 Board Dimensions
0,0 to 2610,0 on M2 Board Dimensions
0,0 to 0,5109 on M2 Board Dimensions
